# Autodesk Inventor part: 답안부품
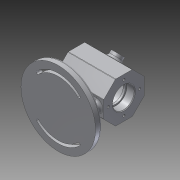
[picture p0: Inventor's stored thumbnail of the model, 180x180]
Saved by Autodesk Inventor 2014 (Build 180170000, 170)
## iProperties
Created: 2017-06
Part Number: 답안부품
Material: 알루미늄 6061
Document SubType Name: Modeling
Designer: net
Density: 2.71 g/cm^3
Appearance: 알루미늄 - 평지
Mass: 562.258 g
Surface Area: 566.111 cm^2
Volume: 207.475 cm^3
Author: net
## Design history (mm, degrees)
sketch "스케치1" dims "d0" = 60
  geometry: L1 (30, -12.426)-(12.426, -30); L2 (12.426, -30)-(-12.426, -30); L3 (-12.426, -30)-(-30, -12.426); L4 (-30, -12.426)-(-30, 12.426); L5 (-30, 12.426)-(-12.426, 30); L6 (-12.426, 30)-(12.426, 30); L7 (12.426, 30)-(30, 12.426); L8 (30, 12.426)-(30, -12.426); 4 further points
  constraints: 16 end point, 2 coincident, 2 horizontal alignment, 1 midpoint, 19 other
extrude "돌출1" new body sketch "스케치1" stored distance "d1" = 70; taper "d2" = 0 deg
sketch "스케치2"
  geometry: L1 (-35, -30)-(-35, 30) reference; L2 (-35, 30)-(35, 30) reference; L3 (35, 30)-(35, -30) reference; L4 (35, -30)-(-35, -30) reference; L5 (-35, 0)-(35, 0); L6 (35, 0)-(35, 16); L7 (35, 16)-(23.3, 16); L8 (23, 15.7)-(23, 14); L9 (23, 14)-(20, 14); L10 (20, 14)-(20, 22); L11 (17, 25)-(-17, 25); L12 (-20, 22)-(-20, 14); L13 (-20, 14)-(-23, 14); L14 (-23, 14)-(-23, 15.7); L15 (-23.3, 16)-(-35, 16); L16 (-35, 0)-(-35, 16); A1 r 0.3 centre (-23.3, 15.7) between (-23, 15.7) and (-23.3, 16); A2 r 0.3 centre (23.3, 15.7) between (23.3, 16) and (23, 15.7); A3 r 3 centre (17, 22) between (20, 22) and (17, 25); A4 r 3 centre (-17, 22) between (-17, 25) and (-20, 22); 6 further points
  constraints: 24 end point, 8 point on circle, 8 point on line, 8 tangent, 5 parallel, 4 centre point, 4 midpoint, 4 perpendicular, 2 equal radius, 1 collinear, 1 vertical alignment
  dimensions: "d3" = 12 distance of L6.end point (23, 16); "d4" = 32 diameter of L7 L5; "d5" = 28 diameter of L9 L5; "d6" = 50 diameter of L11 L5; "d7" = 32 diameter of L15 L5; "d8" = 28 diameter of L13 L5; "d9" = 40 distance of point (20, 25) point (-20, 25); "d10" = 3 distance of L12.end L13.end; "d11" = 0.3 radius of A1; "d12" = 3 radius of A3
revolve "회전1" sketch "스케치2" stored, may be unused: angle "d13" = 90 deg
chamfer "모따기1" distance "d14" = 1; stored, may be unused: second distance "d15" = 2, angle "d16" = 45 deg
sketch "스케치3" dims "d17" = 46
  geometry: C1 r 17 at (0, 0) reference; 2 further points
  constraints: 2 horizontal alignment, 1 coincident, 2 other
hole "구멍1" sketch "스케치3" at (23, 0) diameter "d18" = 3.459; stored, may be unused: countersink angle "d22" = 90 deg, drill point angle "d24" = 118 deg; dims "d19" = 8, "d20" = 4, "d21" = 2, "d23" = 10
sketch "스케치4" dims "d28" = 46
  geometry: C1 r 17 at (0, 0) reference; 2 further points
  constraints: 2 horizontal alignment, 1 coincident, 2 other
hole "구멍2" sketch "스케치4" at (23, 0) diameter "d29" = 3.459; stored, may be unused: countersink angle "d33" = 90 deg, drill point angle "d35" = 118 deg; dims "d30" = 8, "d31" = 4, "d32" = 2, "d34" = 10
node "작업 평면1"
sketch "스케치5"
  geometry: C1 r 55 at (0, 0); 1 further point
  constraints: 1 centre point, 1 coincident
  dimensions: "d40" = 110 diameter of C1
extrude "돌출2" join sketch "스케치5" distance "d41" = 10; taper "d42" = 0 deg
fillet "모깎기1" dims "d43" = 3
sketch "스케치6"
  geometry: L1 (-24, 0)-(24, 0); L2 (-24, -5)-(24, -5); L3 (24, 5)-(-24, 5); C1 r 52 at (0, 0) reference; A1 r 5 centre (-24, 0) between (-24, 5) and (-24, -5); A2 r 5 centre (24, 0) between (24, -5) and (24, 5); 1 further point
  constraints: 8 end point, 4 point on circle, 4 tangent, 2 centre point, 2 coincident, 1 horizontal, 1 midpoint, 1 parallel
  dimensions: "d44" = 48 distance of L1.end L1.start; "d45" = 5 radius of A2
extrude "돌출3" join sketch "스케치6" stored distance "d46" = 10; taper "d47" = 0 deg
fillet "모깎기2" dims "d48" = 5
sketch "스케치7"
  geometry: L1 (-24, -10)-(24, -10) reference; L2 (0, 0)-(41.498, 41.498); L3 (0, 0)-(0, 67.736); L4 (0, 0)-(-48.779, 48.779); C1 r 52 at (0, 0) reference; A1 r 38 centre (0, 0) between (26.87, 26.87) and (-26.87, 26.87); A2 r 48 centre (0, 0) between (33.941, 33.941) and (-33.941, 33.941); A3 r 43 centre (0, 0) between (33.73, 26.67) and (-33.73, 26.67); A4 r 5 centre (30.406, 30.406) between (33.941, 33.941) and (33.73, 26.67); A5 r 5 centre (-30.406, 30.406) between (-33.941, 33.941) and (-33.73, 26.67)
  constraints: 14 point on circle, 6 end point, 5 centre point, 3 coincident, 2 point on line, 1 perpendicular
  dimensions: "d49" = 76 diameter of A1; "d50" = 96 diameter of A2; "d51" = 86 diameter of A3; "d52" = 45 deg angle of L2 L3; "d53" = 45 deg angle of L3 L4
extrude "돌출4" cut sketch "스케치7" distance "d54" = 3; taper "d55" = 0 deg
sketch "스케치8"
  geometry: A1 r 5 centre (-30.406, 30.406) between (-33.941, 33.941) and (-26.87, 26.87) reference; A2 r 38 centre (0, 0) between (26.87, 26.87) and (-26.87, 26.87) reference; A3 r 5 centre (30.406, 30.406) between (26.87, 26.87) and (33.941, 33.941) reference; A4 r 48 centre (0, 0) between (33.941, 33.941) and (-33.941, 33.941) reference; A5 r 2 centre (30.406, 30.406) between (31.82, 31.82) and (31.787, 28.959); A6 r 2 centre (-30.406, 30.406) between (-31.82, 31.82) and (-31.787, 28.959); A7 r 41 centre (0, 0) between (28.991, 28.991) and (-28.991, 28.991); A8 r 45 centre (0, 0) between (31.82, 31.82) and (-31.82, 31.82); A9 r 43 centre (0, 0) between (31.787, 28.959) and (-31.787, 28.959); 2 further points
  constraints: 14 point on circle, 5 centre point, 5 coincident, 2 vertical alignment
  dimensions: "d57" = 4 diameter of A5; "d58" = 4 diameter of A6; "d61" = 82 diameter of A7
extrude "돌출5" cut sketch "스케치8" stored distance "d62" = 3; taper "d63" = 0 deg
fillet "모깎기3" dims "d64" = 1
fillet "모깎기4" dims "d65" = 1
sketch "스케치9"
  geometry: L1 (0, 0.707)-(0, 17.695) reference; L2 (70, 17.988)-(0, 17.988) reference; 2 further points
  constraints: 1 other
  dimensions: "d66" = 35 distance from line of point (35, -12.012) L1; "d67" = 30 distance from line of point (35, -12.012) L2
feature "엠보싱1" sketch "스케치9" dims "d3" = 12, "d4" = 32, "d5" = 28, "d6" = 50, "d7" = 32, "d8" = 28, "d9" = 40, "d10" = 3, "d11" = 0.3, "d12" = 3, "d68" = 0.5, "d69" = 0
sketch "스케치10"
  geometry: L1 (-52, 48)-(-55, 48) reference; L2 (-55, 48)-(-55, 45) reference; L3 (-55, 45)-(-62, 45) reference; L4 (-62, 45)-(-62, 55) reference; L5 (-62, 55)-(-55, 55) reference; L6 (-52, 52)-(-52, 48) reference; L7 (-55, -48)-(-52, -48) reference; L8 (-52, -48)-(-52, -52) reference; L9 (-55, -55)-(-62, -55) reference; L10 (-62, -55)-(-62, -45) reference; L11 (-62, -45)-(-55, -45) reference; L12 (-55, -45)-(-55, -48) reference; L13 (-47, 5)-(-35, 5) reference; L14 (-30, 10)-(-30, 12.012) reference; L15 (-29.707, 12.719)-(-12.719, 29.707) reference; L16 (-12.012, 30)-(12.012, 30) reference; L17 (12.719, 29.707)-(29.707, 12.719) reference; L18 (30, 12.012)-(30, -2.365) reference; L19 (30, -2.365)-(30.5, -2.365) reference; L20 (30.5, -2.365)-(30.5, -2.862) reference; L21 (30.5, -2.862)-(30, -2.862) reference; L22 (30, -2.862)-(30, -12.012) reference; L23 (29.707, -12.719)-(12.719, -29.707) reference; L24 (12.012, -30)-(-12.012, -30) reference; L25 (-12.719, -29.707)-(-29.707, -12.719) reference; L26 (-30, -12.012)-(-30, -10) reference; L27 (-35, -5)-(-47, -5) reference; L28 (-52, -10)-(-52, -38) reference; L29 (-52, -38)-(-55, -38) reference; L30 (-55, -38)-(-55, -41) reference; L31 (-55, -41)-(-62, -41) reference; L32 (-62, -41)-(-62, 41) reference; L33 (-62, 41)-(-55, 41) reference; L34 (-55, 41)-(-55, 38) reference; L35 (-55, 38)-(-52, 38) reference; L36 (-52, 38)-(-52, 10) reference; L37 (0, 0)-(37.213, 0); L38 (0, 0)-(26.163, 26.163); C1 r 25 at (0, 0) reference; A1 r 3 centre (-55, 52) between (-52, 52) and (-55, 55) reference; A2 r 3 centre (-55, -52) between (-55, -55) and (-52, -52) reference; A3 r 5 centre (-47, 10) between (-52, 10) and (-47, 5) reference; A4 r 5 centre (-35, 10) between (-35, 5) and (-30, 10) reference; A5 r 1 centre (-29, 12.012) between (-29.707, 12.719) and (-30, 12.012) reference; A6 r 1 centre (-12.012, 29) between (-12.012, 30) and (-12.719, 29.707) reference; A7 r 1 centre (12.012, 29) between (12.719, 29.707) and (12.012, 30) reference; A8 r 1 centre (29, 12.012) between (30, 12.012) and (29.707, 12.719) reference; A9 r 1 centre (29, -12.012) between (29.707, -12.719) and (30, -12.012) reference; A10 r 1 centre (12.012, -29) between (12.012, -30) and (12.719, -29.707) reference; A11 r 1 centre (-12.012, -29) between (-12.719, -29.707) and (-12.012, -30) reference; A12 r 1 centre (-29, -12.012) between (-30, -12.012) and (-29.707, -12.719) reference; A13 r 5 centre (-35, -10) between (-30, -10) and (-35, -5) reference; A14 r 5 centre (-47, -10) between (-47, -5) and (-52, -10) reference; 1 further point
  constraints: 4 end point, 1 perpendicular
  dimensions: "d72" = 37 distance of L37.start L38.end; "d73" = 45 deg angle of L37 L38
  node "절단 모서리 투영2"
node "작업 평면2"
sketch "스케치11"
  geometry: C1 r 8 at (0, 0); 1 further point
  constraints: 1 centre point, 1 coincident
  dimensions: "d74" = 16 diameter of C1
extrude "돌출6" join sketch "스케치11" stored distance "d75" = 3; taper "d76" = 0 deg
sketch "스케치12"
  geometry: C1 r 8 at (0, 0) reference; C2 r 4 at (0, 0)
  constraints: 1 centre point, 1 coincident
  dimensions: "d77" = 8 diameter of C2
extrude "돌출7" cut sketch "스케치12" stored distance "d78" = 3; taper "d79" = 0 deg
fillet "모깎기5" dims "d80" = 3
chamfer "모따기2" distance "d81" = 1; stored, may be unused: second distance "d82" = 2, angle "d83" = 45 deg
node "솔리드1"
pattern_circular "원형 패턴1" dims angle "d26" = 360 deg
pattern_circular "원형 패턴2" dims angle "d37" = 360 deg
mirror "대칭1"
node "절단 모서리 투영1"
other parameters: "d39" = -62, "d56" = 86
